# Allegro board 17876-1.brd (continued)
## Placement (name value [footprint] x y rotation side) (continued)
RN5504  SRN100J-3-GP  [SMD-ARES4H18]  57.07 80.09 180 top
RN5701  SRN2K2J-1-GP  [ARES2H16]  14.3 78.64 270 top
RN5702  SRN499F-GP  [ARES8-CN24H20]  14.33 80.67 90 top
RN5703  SRN499F-GP  [ARES8-CN24H20]  14.35 83.26 90 top
RN6301  SRN22J-3-GP-U  [ARES8-CN24-UH20]  83.24 94.18 0 top
RN6302  SRN22J-3-GP-U  [ARES8-CN24-UH20]  78.8 92.06 90 top
RN6502  SRN33J-5-GP-U  [SMD-ARES4H18]  26.16 10.29 90 bottom
RN6503  SRN10KJ-5-GP  [ARES2H18]  24.36 10.42 90 bottom
RN6504  SRN2K2J-1-GP  [ARES2H16]  40.82 14.45 0 top
RN6801  SRN0J-6-GP  [SMD-ARES4H20]  54.71 28.3 0 top
RN6802  SRN10KJ-6-GP  [ARES8-CN24-MUH20]  93.29 16.64 0 top
RN6803  SRN0J-6-GP  [SMD-ARES4H20]  53.16 29.64 0 top
RN6901  SRN2K2J-1-GP  [ARES2H16]  97.89 87.33 180 top
RTC1  ACES-CON2-20-GP-U  [50224-0020N-W02]  156.8 100 270 bottom
SD1  SKT-SDCARD-49-GP-U  [PTFBT4-09GLBS1NN4H2]  2.75 26 90 bottom
SPK1  ACES-CON4-29-GP  [50224-0040N-001]  79.5 98.1 90 bottom
SPR1  SPRING-13-GP-U  [SPR7837H229]  134.5 65 270 bottom
SPR2  SPRING-63-GP  [SPR5630H142]  91 82 90 bottom
SPR3  SPRING-98-GP  [SPR5432H83]  140.94 53.5 0 top
SPR4  SPRING-98-GP  [SPR5432H83]  115.56 39.8 0 top
SPR5  SPRING-98-GP  [SPR5432H83]  111.55 79.45 0 top
SPR6  SPRING-98-GP  [SPR5432H83]  113.27 66.88 270 top
TP501  TPAD14-OP-GP  [TPAD14-OP]  94.49 49.99 270 bottom
TP502  TPAD14-OP-GP  [TPAD14-OP]  94.74 51.22 270 bottom
TP801  TPAD14-OP-GP  [TPAD14-OP]  83.87 42.76 90 top
TP802  TPAD14-OP-GP  [TPAD14-OP]  84.87 41.35 90 top
TP803  TPAD14-OP-GP  [TPAD14-OP]  82.62 42.76 90 top
TP804  TPAD14-OP-GP  [TPAD14-OP]  85.6 47.06 90 top
TP805  TPAD14-OP-GP  [TPAD14-OP]  85.62 45.8 90 top
TP806  TPAD14-OP-GP  [TPAD14-OP]  78.82 39.78 180 top
TP807  TPAD14-OP-GP  [TPAD14-OP]  79.4 42.57 90 top
TP808  TPAD14-OP-GP  [TPAD14-OP]  80.37 41.45 180 top
TP809  TPAD14-OP-GP  [TPAD14-OP]  79.68 38.89 180 top
TP810  TPAD14-OP-GP  [TPAD14-OP]  83.11 35.34 180 bottom
TP811  TPAD14-OP-GP  [TPAD14-OP]  84.38 35.34 180 bottom
TP812  TPAD14-OP-GP  [TPAD14-OP]  72.87 47.03 90 top
TP813  TPAD14-OP-GP  [TPAD14-OP]  71.79 45.97 90 top
TP814  TPAD14-OP-GP  [TPAD14-OP]  85.08 42.56 90 top
TP815  TPAD14-OP-GP  [TPAD14-OP]  82.4 39.7 90 top
TP816  TPAD14-OP-GP  [TPAD14-OP]  86.06 35.79 270 bottom
TP1601  TPAD14-OP-GP  [TPAD14-OP]  78.05 64.97 90 bottom
TP1602  TPAD14-OP-GP  [TPAD14-OP]  76.76 65.25 270 bottom
TP1604  TPAD14-OP-GP  [TPAD14-OP]  82.7 57.86 0 top
TP1605  TPAD14-OP-GP  [TPAD14-OP]  84.35 58.35 90 top
TP1608  TPAD14-OP-GP  [TPAD14-OP]  72.64 56.77 90 top
TP1609  TPAD14-OP-GP  [TPAD14-OP]  76.02 66.24 270 bottom
TP1703  TPAD28-2-GP  [TPAD28]  77.99 59.86 90 top
TP1704  TPAD28-2-GP  [TPAD28]  77.37 60.91 90 top
TP1706  TPAD28-2-GP  [TPAD28]  85.91 59.49 90 top
TP1707  TPAD28-2-GP  [TPAD28]  85.97 57.95 90 top
TP1708  TPAD28-2-GP  [TPAD28]  74.88 64.16 0 top
TP1709  TPAD28-2-GP  [TPAD28]  74.88 62.28 0 top
TP1710  TPAD28-2-GP  [TPAD28]  76.12 63.55 0 top
TP1711  TPAD28-2-GP  [TPAD28]  77.62 62.1 0 top
TP2407  TPAD14-OP-GP  [TPAD14-OP]  60.14 28.84 180 bottom
TP2408  TPAD14-OP-GP  [TPAD14-OP]  50.1 23.12 0 top
TP2409  TPAD14-OP-GP  [TPAD14-OP]  63.61 19.5 180 bottom
TP3301  TPAD14-OP-GP  [TPAD14-OP]  13.63 43.16 180 bottom
TP5201  TPAD14-OP-GP  [TPAD14-OP]  33.17 71.68 0 bottom
TP5301  TPAD28-2-GP  [TPAD28]  133.24 41.23 180 bottom
TP5501  TPAD14-OP-GP  [TPAD14-OP]  62.26 85.16 0 top
TP5701  TPAD14-OP-GP  [TPAD14-OP]  13.07 84.97 0 top
TP6101  TPAD14-OP-GP  [TPAD14-OP]  163.65 80.83 0 top
TP6102  TPAD14-OP-GP  [TPAD14-OP]  163.71 85.08 0 top
TP6301  TPAD14-OP-GP  [TPAD14-OP]  87.12 88.88 180 bottom
TP6302  TPAD14-OP-GP  [TPAD14-OP]  88.61 88.32 180 bottom
TP6303  TPAD14-OP-GP  [TPAD14-OP]  87.38 87.66 180 bottom
TP6304  TPAD14-OP-GP  [TPAD14-OP]  87.33 84.48 180 bottom
TP6305  TPAD14-OP-GP  [TPAD14-OP]  57.89 93.78 180 top
TP6306  TPAD14-OP-GP  [TPAD14-OP]  56.59 93.96 180 top
TP6901  TPAD14-OP-GP  [TPAD14-OP]  100.96 84.25 0 top
TP6902  TPAD14-OP-GP  [TPAD14-OP]  95.46 87.71 0 top
TPAD1  PTWO-CON8-16-GP  [196574-08021-3]  35 9.2 180 bottom
U801  NC7WV07P6X-GP  [SC70-6H44]  87.73 23.32 180 bottom
U2401  NPCE385PB0DX-GP  [LQFP128H63]  50.95 27.15 90 bottom
U2404  G2129TL1U-GP  [SC70-6H44]  61.8 34.04 90 bottom
U2501  MX25U6435FM2I-10G-GP  [SOIC8-1H86]  81.18 19.3 0 bottom
U2502  AP2138N-1D5TRG1-GP  [SOT23-2D8-312H58]  57.99 39.73 90 bottom
U2601  NCT7718W-GP  [MSOP8-1H44]  92.3 22.23 0 bottom
U3301  RTS5170-GR-GP  [QFN24-G2D5H40-U]  11.94 40.13 0 bottom
U3601  G524B2T11U-GP  [SOT-23-5H58]  17.83 63.53 90 bottom
U4001  G2898KD1U-GP  [DFN14J32-G255D95H32]  36.37 26.95 270 bottom
U4002  G2898KD1U-GP  [DFN14J32-G255D95H32]  79.22 80.19 180 bottom
U4003  G2042RD1U-GP  [DFN8F3-G2416-1H32]  58.39 66.4 270 bottom
U5501  G517F1T12U-GP  [SOT-23-5H58]  63.25 79.33 0 bottom
U6001  SN75LVCP601RTJR-GP  [QFN20-G2D25H32]  147.22 54.43 180 bottom
U6301  KLMBG4GEND-B031-GP-U  [BGA153G115130-2H40]  86.2 86.5 0 top
U6304  OZ788WR2IBN-A-0-TR-GP  [CSP97G60-1H41]  53.8 90.07 0 top
U6305  MX25L5121EMC-20G-GP  [SOIC8H69]  32.33 83.52 270 bottom
U6901  LNG2DMTR-GP  [LGA12G2H40]  96.57 84.71 270 top
USB1  SKT-USB13-262-GP  [SKT-USB13-160161]  5.39 54.5 90 bottom
WLAN1  SKT-NGFF75P-47-GP  [NFSA0-S6705-TPH4]  158.65 85.5 90 bottom
X1601  XTAL-48MHZ-62-GP  [OSC-3225-4P-4H36]  61.59 41.73 90 bottom
X1701  XTAL-32D768KHZ-98-GP  [SMD49-12H34]  62.79 64.75 0 bottom
X6301  XTAL-30MHZ-37-GP  [S-OSC3-2016H28]  44.63 93.09 270 top

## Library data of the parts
AFTP2901-AFTP2904 AFTP2906-AFTP2909 AFTP3401-AFTP3404 AFTP4301-AFTP4309 AFTP5402 AFTP6101 AFTP6102 AFTP6104 AFTP6105 AFTP6110 AFTP6111 AFTP6113 AFTP6501-AFTP6518 AFTP6520-AFTP6533 AFTP6601-AFTP6607 = AFTE14P-75: tolerance: ZZ.AFT14.101
BATT1 = 3806K-F10N-03L: tolerance: 020.F0667.0010
C303 = C402H22: tolerance: 78.10421.2FLDL; signal model: wistron_C303
C304 = C402H22: tolerance: 78.10421.2FLDL; signal model: wistron_C304
C801 C802 C804 C1701 = C402H22: tolerance: 78.15124.2FL
C803 C1201 C1220 C1224 C2402 C2403 C2429-C2432 C2436 C2438-C2442 C2444-C2446 C2448 C2501 C2601 C2612 C2704 C2706 C2712 C2714 C2718 C2721 C2724 C2735 C2741 C2743 C3301 C3302 C3306 C3606 C3608 C4012 C5508 C6006 C6018 C6102 C6104 C6301 C6303 C6305 C6306 C6309 C6311 C6312 C6315 C6320 C6327 C6330 C6337 C6341 C6349 C6504 C6505 C6702 C6902 EC6001 PC4513 PC4514 PC4622 = C402H22: tolerance: 78.10421.2FLDL
C1001-C1007 C1010 C1011 C1013 C1015 C1017 C1018 C1022 C1024-C1027 C1035 C1040 C1051 C1067 C1068 C1070 C1071 C1073 PC4710 PC4719 PC5207-PC5212 PC5308-PC5311 PC5407 PC5408 PC6301 PC6304 = C603H40: tolerance: 78.22610.5BLDL
C1008 C1032 C1044 C1077 C1212-C1214 C1219 C1227 C1702 C4011 C4027-C4030 PC5418 = C402H22: tolerance: 78.10523.5FL
C1009 C1021 C1033 C1042 = C402H22: tolerance: 78.18134.1FLDL
C1012 C1014 C1016 C1019 C1020 C1023 C1028-C1030 C1034 C1041 C1043 C1064 C1069 C1072 C1074 = C603H40: tolerance: 78.22610.5BL
C1031 C1045 C1049 C1053 C1056 C1059 C1062 C1065 C1075 C1076 C1215-C1218 C1223 C1226 C2443 C2507 C2508 C3308 C3309 C3609 C4009 C4014 C4018 C5509 PC4404 PC4445 PC4446 PC4610 PC4611 PC4902 PC4903 PC4906 PC5202 PC5302 PC5307 PC5316 PC5419 PC5420 PC6305 = C402H22: tolerance: 78.10523.5FLDL
C1036 C1038 C1079 C1211 EC6602 EC6603 PC5214 PC5321 = C402H22: tolerance: 78.10224.2FL
C1037 C1052 C1055 C1061 C1078 C1221 C1222 C2414 C2416 C2602 C2710 C2711 C2715 C2720 C2722 C2723 C2902 C2907 C2908 C6103 C6307 C6308 C6310 C6313 C6314 C6318 C6335 C6340 C6901 PC4904 PC4905 PC5313 PC5315 PC5318 PC5405 PC5406 PC6302 = C603H36: tolerance: 78.10610.5BLDL
C1039 C1046 C1050 C1054 C1057 C1060 C1063 C1080 C1081 C1202 C4001 C4002 C4005 C4006 C5503 EC2901-EC2904 EC3301 EC4308-EC4313 EC6506 EC6601 PC4407-PC4409 PC4602 PC4609 PC4612-PC4614 = C402H22: tolerance: 78.10224.2FLDL
C1047 C1048 C1058 C1225 C2502 C3305 C4004 C4007 C4010 PC5312 = C603H38: tolerance: 78.10610.5BL
C1066 PC4471 = C402H22: tolerance: 078.22423.05FD
C1203 C1206 C1207 C1210 = C402-TO0D2H28: tolerance: 078.10610.05FD
C1204 C1205 C1208 C1209 = C402-TO0D2H28: tolerance: 78.10610.5FL
C1228 C2417 C2428 C2447 C2606 C6016 PC4501 PC4907 PC5411 = C402H22: tolerance: 78.10421.2FL
C1601 C1602 = C402H22: tolerance: 78.15034.1FLDL
C1603 EC3307 = C402H22: tolerance: 78.6R864.1FL
C1703 C1704 C6343 C6344 FC1001-FC1003 FC1201 FC1202 FC2401 FC6002 FC8901-FC8927 = C402H22: tolerance: 78.18034.1FLDL
C2401 C2725 EC2709-EC2711 EC5505 EC5506 EC6002 PC5401 PC6303 = C402H22: tolerance: 78.22034.1FLDL
C2433 C2708 C2740 C2742 = C603H36: tolerance: 78.22523.5BLDL
C2604 = C402H22: tolerance: 78.47124.2FL
C2605 PC4402 PC4403 = C402H22: tolerance: 78.22224.2FLDL
C2613 C2739 EC2905-EC2908 EC6502 PC4603 PC4615 = C402H22: tolerance: 78.10134.1FLDL
C2701 C2713 C2717 C4003 = C603H36: tolerance: 078.10613.05BD
C2702 C2703 C2707 C6302 C6304 = C402H22: tolerance: 078.47510.05FD
C2705 C2709 = C402H22: tolerance: 78.22510.5FLDL
C3303 = C402H22: tolerance: 78.10321.2FL
C3304 C3307 C5511 C5512 C5514 C5521 C6014 C6015 PC4517 PC4518 = C603H36: tolerance: 78.47520.5BLDL
C3505 = C402H22: tolerance: 78.10421.2FLDL; signal model: wistron_C3505
C3506 = C402H22: tolerance: 78.10421.2FLDL; signal model: wistron_C3506
C3508-C3511 = C402H22: tolerance: 78.1R074.1FL
C3601 C3602 = C805H58: tolerance: 078.22613.051D
C4008 C4013 C4015 C4017 PC4701 PC4709 PC4718 PC4720 PC4901 = C402H22: tolerance: 78.33034.1FL
C4016 = C603H36: tolerance: 78.47520.5BL
C5501 = C402H22: tolerance: 78.10421.2FLDL; signal model: wistron_C5501
C5502 C5519 PC4503 PC4504 PC5201 PC5301 = C805H54: tolerance: 78.47522.51LDL
C5504 EC2701-EC2705 EC4303 EC4304 EC4306 EC4314 EC4315 EC5501-EC5503 EC5701 EC8901-EC8905 PC4302 PC4456 PC4463 PC4464 PC4466 PC4605 PC4623 PC4702 PC4703 PC4711 PC4716 PC5203 PC5206 PC5213 PC5303 PC5306 PC5314 = C402H22: tolerance: 78.10422.5FLDL
C5505 = C402H22: tolerance: 78.10421.2FLDL; signal model: wistron_C5505
C5506 = C402H22: tolerance: 78.10421.2FLDL; signal model: wistron_C5506
C5507 = C402H22: tolerance: 78.10421.2FLDL; signal model: wistron_C5507
C5510 = C402H22: tolerance: 78.10421.2FLDL; signal model: wistron_C5510
C5513 = C402H22: tolerance: 78.10421.2FLDL; signal model: wistron_C5513
C5518 EC1701 EC4307 EC4401 = C402H22: tolerance: 78.10034.1FL
C5520 PC4505 PC4507 PC4508 PC4511 PC4512 = C603H35: tolerance: 78.10424.2BLDL
C5701 = C402H22: tolerance: 78.10421.2FLDL; signal model: wistron_C5701
C5702 = C402H22: tolerance: 78.10421.2FLDL; signal model: wistron_C5702
C5703 = C402H22: tolerance: 78.10421.2FLDL; signal model: wistron_C5703
C5704 = C402H22: tolerance: 78.10421.2FLDL; signal model: wistron_C5704
C5705 = C402H22: tolerance: 78.10421.2FLDL; signal model: wistron_C5705
C5706 = C402H22: tolerance: 78.10421.2FLDL; signal model: wistron_C5706
C5707 = C402H22: tolerance: 78.10421.2FLDL; signal model: wistron_C5707
C5708 = C402H22: tolerance: 78.10421.2FLDL; signal model: wistron_C5708
C6001 = C402H22: tolerance: 78.10324.2FLDL; signal model: wistron_C6001
C6002 = C402H22: tolerance: 78.10324.2FLDL; signal model: wistron_C6002
C6003 = C402H22: tolerance: 78.10324.2FLDL; signal model: wistron_C6003
C6004 = C402H22: tolerance: 78.10324.2FLDL; signal model: wistron_C6004
C6005 = C805H50: tolerance: 78.10623.51LDL
C6007 = C402H22: tolerance: 78.10324.2FLDL; signal model: wistron_C6007
C6008 = C402H22: tolerance: 78.10324.2FLDL; signal model: wistron_C6008
C6009 = C402H22: tolerance: 78.10324.2FLDL; signal model: wistron_C6009
C6010 = C402H22: tolerance: 78.10324.2FLDL; signal model: wistron_C6010
C6011-C6013 = C402H22: tolerance: 78.10520.5FLDL
C6017 = C805H54: tolerance: 78.10623.51L
C6019 = C402H22: tolerance: 78.10324.2FLDL; signal model: wistron_C6019
C6020 = C402H22: tolerance: 78.10324.2FLDL; signal model: wistron_C6020
C6021 = C402H22: tolerance: 78.10324.2FLDL; signal model: wistron_C6021
C6022 = C402H22: tolerance: 78.10324.2FLDL; signal model: wistron_C6022
C6345 = C402H22: tolerance: 78.10324.2FLDL; signal model: wistron_C6345
C6346 = C402H22: tolerance: 78.10324.2FLDL; signal model: wistron_C6346
C6347 = C402H22: tolerance: 78.10324.2FLDL; signal model: wistron_C6347
C6348 = C402H22: tolerance: 78.10324.2FLDL; signal model: wistron_C6348
C6701 = C402H22: tolerance: 78.47321.2FL
C6801 PC4304 PC4419 PC4601 PC4620 = C402H22: tolerance: 78.10324.2FLDL
CPU1 = BGA769M24D5H67: tolerance: 071.00AMD.0D0U
D2402 D2403 D4003 = SOD323AKH38: tolerance: 83.R5003.H8H
D2703 D4001 D4004 D5502 PD4410 Q2501 = SOT-23-9H44: tolerance: 75.00054.A7D
D2901 = SC70-2D2-312H44: tolerance: 075.00054.0G7D
D4002 = SOD323-2513AKH36: tolerance: 83.R2004.J8F
D4301-D4303 PD4303 = SOT23-2D4-312H44: tolerance: 75.00099.O7D
D5501 = SOT23-2D4-312H48: tolerance: 75.00054.E7D
D5701 = SOT23-2D4-312H44: tolerance: 83.00056.Y11
DB1 = PAD-87212-1002N: tolerance: ZZ.00PAD.GV1
DCIN1 = 50224-0060N-W01: tolerance: 20.F1639.006
DIMM1 = 40-42271-26001RHF-WD-U: tolerance: 062.10011.M003
EC1601 = C402H22: tolerance: 78.22034.1FL
EC2401 PC5319 = C402H22: tolerance: 78.10134.1FL
EC2403 = SOD882-10D6-1H20: tolerance: 83.05725.0A0
EC2601 EC2602 EC5510 = C402H22: tolerance: 78.33034.1FLDL
EC4301 EC4302 EC4305 PC4436 = C402H22: tolerance: 78.10034.1FLDL
EC5507 = C402H22: tolerance: 78.6R074.1FLDL
EC6501 EC6503 = C402H22: tolerance: 078.4R7B4.01FD
ED501 = SOD-523-4H28: tolerance: 75.05125.070
ED3301-ED3303 = SOT23-2D4-312H46: tolerance: 75.05125.07D
ED3501-ED3504 = D0201H13: tolerance: 83.00525.0A0
ED3505 ED5501 = SOT-6H58: tolerance: 075.09904.0A7C
ED6001 ED6002 = DFN10G2510H22: tolerance: 075.01043.0073
EL3301 = L125100-4PH24: tolerance: 068.24900.2001; signal model: Graser_EL3301
EL3503 = L125100-4PH24: tolerance: 068.24900.2001; signal model: Graser_EL3503
EL4301-EL4304 PR4406 PR4415 PR4432 PR4442 PR4447 PR4457 PR4467 PR4470 PR4471 PR4474-PR4476 PR4502 PR4514 PR4617 PR4621 PR5204 PR5209 PR5307 PR5409 PR5411-PR5413 R501 R704 R816 R818 R821 R823 R1201 R1202 R1208 R1210 R1625 R1632-R1634 R1730 R1731 R1734 R1737 R2413-R2415 R2425 R2435 R2440 R2476 R2477 R2486 R2488 R2494 R2601 R2603 R2609 R2613 R2708 R2709 R2712 R2718 R2720 R2734 R2741 R2752 R3302 R3309 R3311 R3503-R3506 R4001 R4005 R4007 R4008 R4012 R4016 R4301 R5501-R5503 R5702 R5712 R6001 R6502 R6514 R6515 = 0R0402-PAD: tolerance: ZZ.R0402.ZZZ
EL5501 = L125100-4PH24: tolerance: 068.24900.2001; signal model: wistron_EL5501
EL5502 = L125100-4PH24: tolerance: 068.24900.2001; signal model: wistron_EL5502
EL6101 = L125100-4PH24: tolerance: 068.24900.2001; signal model: wistron_EL6101
EL6602 = L125100-4PH24: tolerance: 068.24900.2001; signal model: wistron_EL6602
EL6603 = L125100-4PH24: tolerance: 068.24900.2001; signal model: wistron_EL6603
EL6604 = L125100-4PH24: tolerance: 068.24900.2001; signal model: wistron_EL6604
ER5714-ER5717 R802 = R402H16: tolerance: 64.15005.6DL
F5501 = POLYSW-4633-UH43: tolerance: 69.50007.A31
F5502 F5503 F5701 = POLYSW-2114H30: tolerance: 69.48001.081
FC1601 = C402H22: tolerance: 78.8R064.1FLDL
G1701 G1702 = CON2O-U: tolerance: ZZ.CON2O.XXX
H1 = HOLE354R237: tolerance: ZZ.PAD01.041
H4 H9 = HOLE335R197: tolerance: ZZ.00PAD.7L1
H10-H13 = HOLE276R178: tolerance: ZZ.00PAD.N11
H14 = HOLE335R142: tolerance: ZZ.00PAD.XXX
HDA27 = QFN40J5-G3D75H36: tolerance: 071.03204.0003
HDD1 = 15-02330-3A03-A: tolerance: 022.10019.00F1
HDMI1 = SKT-HDMI23-188125-5: tolerance: 022.10025.00F1
HDT1 = DM-ASP-137098-05-01: tolerance: ZZ.F1722.02001
IOBD1 = 132F44-000000-A2-R: tolerance: 020.K0228.0044
KB1 = 50699-03001-W01: tolerance: 020.K0254.0030
LCD1 = 51540-04001-W01: tolerance: 20.K0678.040
LIDSW1 = SOT23-2D8-123H52: tolerance: 74.05712.0BB
PC4301 PC4435 = C603H36: tolerance: 078.10524.05BD
PC4303 PC4305 = C402H22: tolerance: 78.10324.2FL
PC4306 PC4401 PC4410 PC4411 PC4418 PC4427 PC4438 PC4452 PC4453 PC4459 PC4509 PC4510 PC4704-PC4707 PC4712-PC4715 PC5204 PC5205 PC5304 PC5305 = C805H58: tolerance: 78.10622.51LDL
PC4405 = C402H22: tolerance: 78.22321.2FL
PC4406 = C402H22: tolerance: 78.56124.2FLDL
PC4431 = C603H36: tolerance: 78.22422.2BLDL
PC4433 = C603H36: tolerance: 78.47422.5BLDL
PC4461 PC4462 PC4467 PC4468 = C402H22: tolerance: 78.22224.L0L
PC4502 = C402H22: tolerance: 78.68034.1FL
PC4506 = C805H56: tolerance: 78.10622.51L
PC4515 PC4516 = C402H22: tolerance: 78.18034.1FL
PC4604 PC4616 = C402H22: tolerance: 078.39124.02FD
PC4606 PC4618 = C402H22: tolerance: 078.33322.02FD
PC4607 PC4619 = C402H22: tolerance: 078.47322.02FD
PC4608 PC4617 = C402H22: tolerance: 78.33124.2FLDL
PC4621 = C402H22: tolerance: 78.33124.2FL
PC4708 PC4717 = C402H22: tolerance: 078.22422.05FD
PC5317 PC5320 PC5410 = C402H22: tolerance: 78.10422.5FL
PC5412 = C402H22: tolerance: 78.68124.2FL
PD4301 = DO214AAAKH97: tolerance: 83.P6SMB.JAG
PD4302 = SOD123AK-2H43: tolerance: 83.SMF18.AAH
PD4304 = SOT23-2D4-312H46: tolerance: 75.04024.07D
PD4404 = SOD323AKH44: tolerance: 83.00355.G1F
PD5201 PD5301 = SOD323AKH40: tolerance: 083.04024.0AA1
PG4407 PG4426 PG4428 PG4429 PG4524 PG4525 PG4602-PG4608 PG4903 PG5201-PG5211 PG5301-PG5312 PG5314 PG5315 PG5401-PG5406 PG5411 = GAP-CLOSE-PWR-3: tolerance: ZZ.CLOSE.001
PG4501-PG4523 PG4601 PG4609-PG4611 PG4701-PG4713 PG4901 PG4902 PG5212 PG5313 = GAP-CLOSE-PWR: tolerance: ZZ.CLOSE.011
PL4401 = L7066-1830-UH119: tolerance: 68.4R71A.20H
PL4501 PL4502 = L7066-1830-UH119: tolerance: 68.2R210.20B
PL4701 PL4702 = L7366-1930H119: tolerance: 068.R1510.2041
PL5201 PL5301 = L7066-1830-UH119: tolerance: 68.1R01A.20B
PL5401 = L2520-D620H48: tolerance: 068.1R010.1281
PL6301 = L2520-D620H48: tolerance: 068.2R210.1231
PQ4301 = SOT23DGS2D4H48: tolerance: 084.00301.0031
PQ4302 Q2601 Q5501 Q5503 Q5708 = SOT23CBE2D4H44: tolerance: 84.T3904.H11
PQ4304 PQ4415 = SC70-2D2-312H44: tolerance: 84.00024.A1K
PQ4305 PQ4416 = SC70-2D2-312H44: tolerance: 84.00024.01K
PQ4309 PQ4402 PQ4412 Q2402 Q2403 Q2405 Q2502 Q2505 Q2507 Q2603 Q2901 Q4001 Q5401 Q5701 Q5707 Q6502 = SOT23DGS2D4H44: tolerance: 84.2N702.J31
PQ4401 PQ4408 PU4301 = PPAK-8P-3232H36: tolerance: 84.07403.037
PQ4405 PQ4414 Q1701 Q1702 Q2604 Q7001 = SOT-363H44: tolerance: 75.27002.F7C
PQ4413 Q2401 = SOT23CBE2D4H44: tolerance: 84.T3906.E11
PQ4901 Q6507 = SOT-363H44: tolerance: 84.2N702.A3F
PR4302 = R402H16: tolerance: 64.15025.6DL
PR4303 PR5312 PR5314 PR5414 R1613-R1616 R1620 R1621 R1636 R1702 R1703 R1707-R1710 R1713 R1715 R1717 R1718 R1723 R1724 R1733 R1735 R1738 R1757 R1759-R1761 R2001-R2006 R2400 R2407 R2420-R2423 R2427 R2428 R2436 R2444 R2463 R2471 R2472 R2474 R2478 R2490 R2497 R2499 R2507 R3307 R4006 R4010 R4011 R4013 R5527 R5701 R6002-R6009 R6111 R6112 R6309 R6347 R6348 R6354-R6357 R6359 R6364 R6902 R6905 R7005 = R402H16: tolerance: 63.10334.1DL
PR4306 R5516 R5521 R5526 R6512 = R402H16: tolerance: 63.22234.1DL
PR4307 R1729 R5504 R6804 = R402H16: tolerance: 63.33034.1DL
PR4309 = R603H22: tolerance: 63.24434.15L
PR4310 = R603H22: tolerance: 63.47333.15L
PR4311 PR4409 PR4417 PR4431 PR4441 PR4472 PR4478 PR4513 PR5203 PR5303 PR5407 R1719 R1747 R1758 R2410 R2434 R2442 R2473 R2516 R2518 R2702 R2710 R2716 R2717 R2905 R3605 R5505-R5508 R5522 R5709 R5719 R6345 R6520 R6701 R7002 = R402H16: tolerance: 63.10434.1DL
PR4312 PR4444 R504 R801 R809 R811 R812 R822 R1206 R1711 R1748 R2419 R2443 R2468 R2493 R2501 R2506 R2735 R2921 R2922 R4003 R6503 R6516 = R402H16: tolerance: 63.10234.1DL
PR4316 = R1206H28: tolerance: 63.33232.11L
PR4401 PR4402 R2711 R5711 = R402H16: tolerance: 64.20035.6DL
PR4403 PR4507 = R402H16: tolerance: 64.95325.6DL
PR4404 = R402H16: tolerance: 64.82525.6DL
PR4405 = R402H16: tolerance: 64.16535.6DL
PR4407 = R402H14: tolerance: 64.10005.6DL
PR4410 = R402H16: tolerance: 64.71515.6DL
PR4412 = NTC-402H24-U: tolerance: 69.60028.001
PR4413 PR4436 PR4439 PR4450 PR4451 R2438 = R402H16: tolerance: 64.10035.6DL
PR4416 = R402H16: tolerance: 64.23725.6DL
PR4418 = R402H16: tolerance: 64.19135.6DL
PR4420 PR4422 PR4435 PR4448 PR4449 PR4508 PR4512 PR4611 PR4620 PR4630 PR4901 PR5208 PR5309 PR5316 = R402H16: tolerance: 64.10025.6DL
PR4426 PR4443 = R3720H40: tolerance: 64.R0105.7FL
PR4428 R2409 R2703-R2706 R2715 R2742 R2743 R2745 R2747 R2749 R2906 R2907 R2909 R2911 R6105 R6324 R6325 = 0R0603-PAD: tolerance: ZZ.R0603.ZZZ
PR4433 = R402H16: tolerance: 64.68035.6DL
PR4434 = R402H16: tolerance: 64.30035.L0L
PR4437 PR4456 PR4468 = R402H16: tolerance: 64.2R005.6DL
PR4438 = R603H22: tolerance: 64.4R705.55L
PR4440 = R603H22: tolerance: 63.20333.15L
PR4445 R6360 R6361 = R402H16: tolerance: 63.47434.1DL
PR4446 PR4481 PR4509 PR4510 PR5206 PR5306 PR5319 PR5410 R1205 R1207 R1209 R1211 R1635 R1756 R2498 R2513-R2515 R2517 R2602 R2607 R4004 R4009 R4015 R5524 R6106-R6110 R6113 R6327 R6328 R6501 R6510 R6513 R6518 R6803 R6901 R6903 R6933-R6937 R7001 = R402H16: tolerance: 63.R0034.1DL
PR4452 R5710 = R402H16: tolerance: 64.15035.6DL
PR4454 = R805H24: tolerance: 64.10005.16L
PR4477 R1203 R1204 R1601 R1602 R1609 R1610 = R402H16: tolerance: 64.10015.6DL
PR4503 PR4504 = R603H22: tolerance: 64.1R505.55L
PR4505 = R402H16: tolerance: 64.69815.6DL
PR4506 = R402H16: tolerance: 64.13735.6DL
PR4511 = R402H16: tolerance: 64.15425.6DL
PR4601 PR5201 PR5301 R2908 R2910 = R402H14: tolerance: 64.10R05.6DL
PR4602 PR4624 = R402H16: tolerance: 64.30105.6DL
PR4603 = R402H16: tolerance: 64.39005.6DL
PR4604 PR4627 = R402H16: tolerance: 64.68025.6DL
PR4605 = R402H16: tolerance: 64.21515.6DL
PR4606 PR4625 PR4632 = R402H16: tolerance: 64.26115.6DL
PR4607 PR4628 R803 R2606 = R402H16: tolerance: 64.20015.6DL
PR4608 = R402H16: tolerance: 64.34025.6DL
PR4609 PR4633 = R402H16: tolerance: 64.11025.6DL
PR4610 PR4635 = NTC-402H22-U: tolerance: 69.60011.201
PR4612 PR4622 R1603 = R402H16: tolerance: 64.11825.6DL
PR4613 PR4623 = NTC-402H22-U: tolerance: 69.60011.101
PR4614 PR4626 = R402H16: tolerance: 64.27425.6DL
PR4615 PR4618 = R402H16: tolerance: 64.13335.6DL
PR4616 = R603H22: tolerance: 63.1R033.15L
PR4619 R808 = R402H16: tolerance: 63.30134.1DL
PR4629 = R402H16: tolerance: 64.21035.6DL
PR4631 PR4634 = R402H14: tolerance: 63.10034.1DL
PR4636 = R402H16: tolerance: 64.48705.6DL
PR4701 PR4704 R2408 = R603H22: tolerance: 64.2R205.55L
PR4702 PR4705 = R402H16: tolerance: 64.36515.6DL
PR4703 PR4706 = R402H16: tolerance: 64.1R005.6DL
PR4902 = R402H16: tolerance: 64.39015.6DL
PR4903 = R402H16: tolerance: 64.30015.6DL
PR5202 = R402H16: tolerance: 64.82015.6DL
PR5205 PR5304 = R402H16: tolerance: 64.51035.6DL
PR5207 = R402H16: tolerance: 64.26715.6DL
PR5210 PR5317 = R603H22: tolerance: 64.2R005.55L
PR5211 PR5318 = R805H24: tolerance: 64.2R205.16L
PR5302 = R402H16: tolerance: 64.64915.6DL
PR5308 = R402H16: tolerance: 64.60415.6DL
PR5310 = R603H22: tolerance: 63.5R133.15L
PR5311 PR5313 R2701 R2707 R2751 = 0R0805-PAD: tolerance: ZZ.R0805.ZZZ
PR5315 = R402H16: tolerance: 64.21525.6DL
PR5403 = R402H16: tolerance: 64.10235.6DL
PR5405 = R402H16: tolerance: 64.51025.6DL
PR5406 = R402H16: tolerance: 64.18025.6DL
PR6301 = R402H16: tolerance: 64.21025.6DL
PR6302 = R402H16: tolerance: 64.14325.6DL
PR6303 R2914 = R603H22: tolerance: 63.R0033.L0L
PT4501 PT4502 = CT7343H83: tolerance: 077.51571.0001
PT4701 PT4702 PT4705 PT4706 = CT7343H83: tolerance: 79.33719.20C
PT4707 PT4708 = CT7343H83: tolerance: 79.33612.20L
PU4401 = QFN32J4-G2D7H42: tolerance: 074.88739.0073
PU4411 PU4412 PU4502-PU4504 = PPAK-8P-3232H36: tolerance: 084.07408.0037
PU4501 = QFN20-G1D75H32: tolerance: 074.06575.0A43
PU4505 = PPAK-8P-3232H36: tolerance: 84.07506.037
PU4601 = QFN40-G3D5H32: tolerance: 74.62771.033
PU4701 PU4702 PU4705 PU4706 = PPAK-8P-G5324H44-COLAY: tolerance: ZZ.00215.037
PU4901 = SOIC8-G3530H63: tolerance: 074.05337.0031
PU5201 PU5301 = QFN32J4-G3PH32: tolerance: 074.05388.0043
PU5302 = SOIC8-G3530H63: tolerance: 074.05934.003D
PU5401 = DFN8-G125065H32: tolerance: 074.05797.0073
PU5402 = SOT-23-5H40: tolerance: 074.09078.003F
PU6301 = DFN8G2-G1711H26: tolerance: 74.00232.033
Q801 Q6508 = SOT-363H44: tolerance: 075.00138.0A7C
Q2404 Q2506 Q6503 Q6504 = SOT23DGS2D4H48: tolerance: 084.02421.0031
Q5703 = SOT23DGS2D4H48: tolerance: 084.00301.0031; signal model: wistron_Q5703
Q5705 = SOT23DGS2D4H48: tolerance: 084.00301.0031; signal model: wistron_Q5705
Q6301 = SOT23DGS2D4H48: tolerance: 84.05067.031
Q6501 = SOT23CBE2D4H44: tolerance: 084.00144.0B11
R301 R302 = R402H16: tolerance: 64.19605.6DL
R503 = R402H16: tolerance: 64.39R25.6DL
R810 = 0R0402-PAD: tolerance: ZZ.R0402.ZZZ; signal model: Graser_R810
R813 = 0R0402-PAD: tolerance: ZZ.R0402.ZZZ; signal model: Graser_R813
R820 = 0R0402-PAD: tolerance: ZZ.R0402.ZZZ; signal model: Graser_R820
R1607 = 0R0402-PAD: tolerance: ZZ.R0402.ZZZ; signal model: wistron_R1607
R1608 = 0R0402-PAD: tolerance: ZZ.R0402.ZZZ; signal model: wistron_R1608
R1611 = 0R0402-PAD: tolerance: ZZ.R0402.ZZZ; signal model: wistron_R1611
R1612 = R402H16: tolerance: 63.R0034.1DL; signal model: wistron_R1612
R1617 = 0R0402-PAD: tolerance: ZZ.R0402.ZZZ; signal model: wistron_R1617
R1618 = 0R0402-PAD: tolerance: ZZ.R0402.ZZZ; signal model: wistron_R1618
R1619 = 0R0402-PAD: tolerance: ZZ.R0402.ZZZ; signal model: wistron_R1619
R1624 R4014 R6353 = R402H16: tolerance: 63.10534.1DL
R1629 = R402H16: tolerance: 63.33034.1DL; signal model: wistron_R1629
R1630 = 0R0402-PAD: tolerance: ZZ.R0402.ZZZ; signal model: wistron_R1630
R1631 = 0R0402-PAD: tolerance: ZZ.R0402.ZZZ; signal model: wistron_R1631
R1721 = R402H16: tolerance: 63.15334.1DL
R1745 = R603H22: tolerance: 63.20634.15L
R1746 = R402H16: tolerance: 63.20334.1DL
R2007-R2012 R2615 = R402H16: tolerance: 63.20234.1DL
R2437 R2492 = R402H16: tolerance: 63.47334.1DL
R2465 = R402H16: tolerance: 64.22125.6DL
R2475 = R402H16: tolerance: 63.82234.1DL
R2489 R2491 = R402H16: tolerance: 63.33434.1DL
R2505 = R402H16: tolerance: 63.10634.1DL
R2540 R2912 R2928 R6010-R6013 R6313 R6346 R6504 = R402H16: tolerance: 63.47234.1DL
R2604 R2612 = NTC-603H38: tolerance: 69.60035.041
R2605 = R402H16: tolerance: 64.18725.6DL
R2608 R2614 = R402H16: tolerance: 64.24925.6DL
R2753 = 0R0402-PAD: tolerance: ZZ.R0402.ZZZ; signal model: wistron_R2753
R2901-R2904 = L1608-UH38: tolerance: 68.00230.041
R3303 = 0R0402-PAD: tolerance: ZZ.R0402.ZZZ; signal model: wistron_R3303
R3304 = R402H16: tolerance: 64.62015.6DL
R4002 = R402H16: tolerance: 63.20434.1DL
R5533 R5534 R6014 R6015 = R805H24: tolerance: 63.R0031.16L
R6016 = R402H16: tolerance: 63.R0034.1DL; signal model: wistron_R6016
R6017 = R402H16: tolerance: 63.R0034.1DL; signal model: wistron_R6017
R6018 = R402H16: tolerance: 63.R0034.1DL; signal model: wistron_R6018
R6019 = R402H16: tolerance: 63.R0034.1DL; signal model: wistron_R6019
R6101 = 0R0402-PAD: tolerance: ZZ.R0402.ZZZ; signal model: wistron_R6101
R6104 = 0R0402-PAD: tolerance: ZZ.R0402.ZZZ; signal model: wistron_R6104
R6312 = R402H16: tolerance: 63.22034.1DL; signal model: wistron_R6312
R6343 = R402H16: tolerance: 63.R0034.1DL; signal model: wistron_R6343
R6344 = R402H16: tolerance: 63.22034.1DL; signal model: wistron_R6344
R6365 = R402H16: tolerance: 63.68134.1DL
R6505 R6506 = R402H16: tolerance: 63.22134.1DL
R6801 = R402H16: tolerance: 63.R0034.1DL; signal model: wistron_R6801
R6802 = R402H16: tolerance: 63.R0034.1DL; signal model: wistron_R6802
RN803 RN804 = ARES8-CN24H20: tolerance: 66.10236.08L
RN806-RN809 RN1709 = SMD-ARES4H18: tolerance: 66.10236.04L
RN810 = SMD-ARES4H20: tolerance: 66.R0036.04L
RN811 = SMD-ARES4H18: tolerance: 66.47236.04L
RN1601 RN1705 RN1710 RN2407 RN6503 = ARES2H18: tolerance: 66.10336.04L
RN1603 = SMD-ARES4H20: tolerance: 66.R0036.04L; signal model: Graser_RN1603
RN1604 = SMD-ARES4H20: tolerance: 66.R0036.04L; signal model: wistron_RN1604
RN1605 = SMD-ARES4H20: tolerance: 66.R0036.04L; signal model: wistron_RN1605
RN1606 = SMD-ARES4H20: tolerance: 66.R0036.04L; signal model: wistron_RN1606
RN1701 RN1703 RN1704 RN2401 RN2404 RN2601 RN2901 RN5701 RN6504 RN6901 = ARES2H16: tolerance: 66.22236.04L
RN1706 RN2403 = SMD-ARES4: tolerance: 66.10436.04L
RN1707 = ARES8-CN24-UH20: tolerance: 66.33036.A8L; signal model: wistron_RN1707
RN1708 = SMD-ARES4H18: tolerance: 66.15336.04L
RN2405 = SMD-ARES4H20: tolerance: 66.R0036.04L; signal model: wistron_RN2405
RN2406 = SMD-ARES4H20: tolerance: 66.R0036.04L; signal model: wistron_RN2406
RN4301 RN4302 RN5503 RN5504 = SMD-ARES4H18: tolerance: 66.10136.04L
RN5502 RN6502 = SMD-ARES4H18: tolerance: 66.33036.04L
RN5702 RN5703 = ARES8-CN24H20: tolerance: 66.49156.08L
RN6301 = ARES8-CN24-UH20: tolerance: 66.22036.08L; signal model: wistron_RN6301
RN6302 = ARES8-CN24-UH20: tolerance: 66.22036.08L; signal model: wistron_RN6302
RN6801 = SMD-ARES4H20: tolerance: 66.R0036.04L; signal model: wistron_RN6801
RN6802 = ARES8-CN24-MUH20: tolerance: 66.10336.08L
RN6803 = SMD-ARES4H20: tolerance: 66.R0036.04L; signal model: wistron_RN6803
RTC1 = 50224-0020N-W02: tolerance: 20.F1639.002
SD1 = PTFBT4-09GLBS1NN4H2: tolerance: 062.10002.0081
SPK1 = 50224-0040N-001: tolerance: 20.F1639.004
SPR1 = SPR7837H229: tolerance: 34.43E24.001
SPR2 = SPR5630H142: tolerance: 34.4Y806.001
SPR3-SPR6 = SPR5432H83: tolerance: 34.34S02.002
TP501 TP502 TP801-TP816 TP1601 TP1602 TP1604 TP1605 TP1608 TP1609 TP2407-TP2409 TP3301 TP5201 TP5501 TP5701 TP6101 TP6102 TP6301-TP6306 TP6901 TP6902 = TPAD14-OP: tolerance: ZZ.PAD14.001
TP1703 TP1704 TP1706-TP1711 TP5301 = TPAD28: tolerance: ZZ.PAD28.XXX
TPAD1 = 196574-08021-3: tolerance: 020.K0255.0008
U801 = SC70-6H44: tolerance: 73.7WV07.00J
U2401 = LQFP128H63: tolerance: 071.00385.0A0G
U2404 = SC70-6H44: tolerance: 73.02129.02J
U2501 = SOIC8-1H86: tolerance: 72.25643.B01
U2502 = SOT23-2D8-312H58: tolerance: 74.02138.03B
U2601 = MSOP8-1H44: tolerance: 74.07718.0B9
U3301 = QFN24-G2D5H40-U: tolerance: 71.05170.003
U3601 = SOT-23-5H58: tolerance: 074.00524.0C9F
U4001 U4002 = DFN14J32-G255D95H32: tolerance: 074.02898.0093
U4003 = DFN8F3-G2416-1H32: tolerance: 074.02042.0093
U5501 = SOT-23-5H58: tolerance: 074.51712.009F
U6001 = QFN20-G2D25H32: tolerance: 71.75601.003
U6301 = BGA153G115130-2H40: tolerance: 072.KMBG4.0C0U
U6304 = CSP97G60-1H41: tolerance: 071.07882.000U
U6305 = SOIC8H69: tolerance: 72.25512.J01
U6901 = LGA12G2H40: tolerance: 074.LNG2D.00BZ
USB1 = SKT-USB13-160161: tolerance: 022.10005.02V1
WLAN1 = NFSA0-S6705-TPH4: tolerance: 062.10003.0141
X1601 = OSC-3225-4P-4H36: tolerance: 082.30028.0101
X1701 = SMD49-12H34: tolerance: 082.30003.0301
X6301 = S-OSC3-2016H28: tolerance: 082.30002.0111

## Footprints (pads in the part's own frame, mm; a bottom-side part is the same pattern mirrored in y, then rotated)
0R0402-PAD
  custom 0.127x0.127 smd: 1(0,0.432) 2(0,-0.432)
0R0603-PAD
  custom 0.254x0.254 smd: 1(0,0.66) 2(0,-0.66)
0R0805-PAD
  rect 1.549x1.346 smd: 1(0,0.838) 2(0,-0.838)
15-02330-3A03-A
  oval 1.727x2.794 hole 1.016x2.083: 23(-18.6,0) 24(18.6,0)
  oval 1.041x1.168 hole 0.762: P1(-1.905,0.4) P2(-0.635,0.4) P3(0.635,0.4) P4(1.905,0.4) P5(3.175,0.4) P6(4.445,0.4) P7(5.715,0.4) P8(6.985,0.4) P9(8.255,0.4) P10(9.525,0.4) P11(10.795,0.4) P12(12.065,0.4) P13(13.335,0.4) P14(14.605,0.4) P15(15.875,0.4) S1(-15.875,0.4) S2(-14.605,0.4) S3(-13.335,0.4) S4(-12.065,0.4) S5(-10.795,0.4) S6(-9.525,0.4) S7(-8.255,0.4)
40-42271-26001RHF-WD-U
  round 0.254 hole 1.6 unplated: (-34.4,0)
  round 0.254 hole 1.118 unplated: (34.4,0)
  custom 0.089x0.089 smd: 1(-33.375,-4.1) 2(-33.125,4.1) 3(-32.875,-4.1) 4(-32.625,4.1) 5(-32.375,-4.1) 6(-32.125,4.1) 7(-31.875,-4.1) 8(-31.625,4.1) 9(-31.375,-4.1) 10(-31.125,4.1) 11(-30.875,-4.1) 12(-30.625,4.1) 13(-30.375,-4.1) 14(-30.125,4.1) 15(-29.875,-4.1) 16(-29.625,4.1) 17(-29.375,-4.1) 18(-29.125,4.1) 19(-28.875,-4.1) 20(-28.625,4.1) 21(-28.375,-4.1) 22(-28.125,4.1) 23(-27.875,-4.1) 24(-27.625,4.1) 25(-27.375,-4.1) 26(-27.125,4.1) 27(-26.875,-4.1) 28(-26.625,4.1) 29(-26.375,-4.1) 30(-26.125,4.1) 31(-25.875,-4.1) 32(-25.625,4.1) 33(-25.375,-4.1) 34(-25.125,4.1) 35(-24.875,-4.1) 36(-24.625,4.1) 37(-24.375,-4.1) 38(-24.125,4.1) 39(-23.875,-4.1) 40(-23.625,4.1) 41(-23.375,-4.1) 42(-23.125,4.1) 43(-22.875,-4.1) 44(-22.625,4.1) 45(-22.375,-4.1) 46(-22.125,4.1) 47(-21.875,-4.1) 48(-21.625,4.1) 49(-21.375,-4.1) 50(-21.125,4.1) 51(-20.875,-4.1) 52(-20.625,4.1) 53(-20.375,-4.1) 54(-20.125,4.1) 55(-19.875,-4.1) 56(-19.625,4.1) 57(-19.375,-4.1) 58(-19.125,4.1) 59(-18.875,-4.1) 60(-18.625,4.1) 61(-18.375,-4.1) 62(-18.125,4.1) 63(-17.875,-4.1) 64(-17.625,4.1) 65(-17.375,-4.1) 66(-17.125,4.1) 67(-16.875,-4.1) 68(-16.625,4.1) 69(-16.375,-4.1) 70(-16.125,4.1) 71(-15.875,-4.1) 72(-15.625,4.1) 73(-15.375,-4.1) 74(-15.125,4.1) 75(-14.875,-4.1) 76(-14.625,4.1) 77(-14.375,-4.1) 78(-14.125,4.1) 79(-13.875,-4.1) 80(-13.625,4.1) 81(-13.375,-4.1) 82(-13.125,4.1) 83(-12.875,-4.1) 84(-12.625,4.1) 85(-12.375,-4.1) 86(-12.125,4.1) 87(-11.875,-4.1) 88(-11.625,4.1) 89(-11.375,-4.1) 90(-11.125,4.1) 91(-10.875,-4.1) 92(-10.625,4.1) 93(-10.375,-4.1) 94(-10.125,4.1) 95(-9.875,-4.1) 96(-9.625,4.1) 97(-9.375,-4.1) 98(-9.125,4.1) 99(-8.875,-4.1) 100(-8.625,4.1) 101(-8.375,-4.1) 102(-8.125,4.1) 103(-7.875,-4.1) 104(-7.625,4.1) 105(-7.375,-4.1) 106(-7.125,4.1) 107(-6.875,-4.1) 108(-6.625,4.1) 109(-6.375,-4.1) 110(-6.125,4.1) 111(-5.875,-4.1) 112(-5.625,4.1) 113(-5.375,-4.1) 114(-5.125,4.1) 115(-4.875,-4.1) 116(-4.625,4.1) 117(-4.375,-4.1) 118(-4.125,4.1) 119(-3.875,-4.1) 120(-3.625,4.1) 121(-3.375,-4.1) 122(-3.125,4.1) 123(-2.875,-4.1) 124(-2.625,4.1) 125(-2.375,-4.1) 126(-2.125,4.1) 127(-1.875,-4.1) 128(-1.625,4.1) 129(-1.375,-4.1) 130(-1.125,4.1) 131(-0.875,-4.1) 132(-0.625,4.1) 133(-0.375,-4.1) 134(-0.125,4.1) 135(0.125,-4.1) 136(0.375,4.1) 137(0.625,-4.1) 138(0.875,4.1) 139(1.125,-4.1) 140(1.375,4.1) 141(1.625,-4.1) 142(1.875,4.1) 143(2.125,-4.1) 144(2.375,4.1) 145(4.625,-4.1) 146(4.875,4.1) 147(5.125,-4.1) 148(5.375,4.1) 149(5.625,-4.1) 150(5.875,4.1) 151(6.125,-4.1) 152(6.375,4.1) 153(6.625,-4.1) 154(6.875,4.1) 155(7.125,-4.1) 156(7.375,4.1) 157(7.625,-4.1) 158(7.875,4.1) 159(8.125,-4.1) 160(8.375,4.1) 161(8.625,-4.1) 162(8.875,4.1) 163(9.125,-4.1) 164(9.375,4.1) 165(9.625,-4.1) 166(9.875,4.1) 167(10.125,-4.1) 168(10.375,4.1) 169(10.625,-4.1) 170(10.875,4.1) 171(11.125,-4.1) 172(11.375,4.1) 173(11.625,-4.1) 174(11.875,4.1) 175(12.125,-4.1) 176(12.375,4.1) 177(12.625,-4.1) 178(12.875,4.1) 179(13.125,-4.1) 180(13.375,4.1) 181(13.625,-4.1) 182(13.875,4.1) 183(14.125,-4.1) 184(14.375,4.1) 185(14.625,-4.1) 186(14.875,4.1) 187(15.125,-4.1) 188(15.375,4.1) 189(15.625,-4.1) 190(15.875,4.1) 191(16.125,-4.1) 192(16.375,4.1) 193(16.625,-4.1) 194(16.875,4.1) 195(17.125,-4.1) 196(17.375,4.1) 197(17.625,-4.1) 198(17.875,4.1) 199(18.125,-4.1) 200(18.375,4.1) 201(18.625,-4.1) 202(18.875,4.1) 203(19.125,-4.1) 204(19.375,4.1) 205(19.625,-4.1) 206(19.875,4.1) 207(20.125,-4.1) 208(20.375,4.1) 209(20.625,-4.1) 210(20.875,4.1) 211(21.125,-4.1) 212(21.375,4.1) 213(21.625,-4.1) 214(21.875,4.1) 215(22.125,-4.1) 216(22.375,4.1) 217(22.625,-4.1) 218(22.875,4.1) 219(23.125,-4.1) 220(23.375,4.1) 221(23.625,-4.1) 222(23.875,4.1) 223(24.125,-4.1) 224(24.375,4.1) 225(24.625,-4.1) 226(24.875,4.1) 227(25.125,-4.1) 228(25.375,4.1) 229(25.625,-4.1) 230(25.875,4.1) 231(26.125,-4.1) 232(26.375,4.1) 233(26.625,-4.1) 234(26.875,4.1) 235(27.125,-4.1) 236(27.375,4.1) 237(27.625,-4.1) 238(27.875,4.1) 239(28.125,-4.1) 240(28.375,4.1) 241(28.625,-4.1) 242(28.875,4.1) 243(29.125,-4.1) 244(29.375,4.1) 245(29.625,-4.1) 246(29.875,4.1) 247(30.125,-4.1) 248(30.375,4.1) 249(30.625,-4.1) 250(30.875,4.1) 251(31.125,-4.1) 252(31.375,4.1) 253(31.625,-4.1) 254(31.875,4.1) 255(32.125,-4.1) 256(32.375,4.1) 257(32.625,-4.1) 258(32.875,4.1) 259(33.125,-4.1) 260(33.375,4.1)
  rect 3.505x4.597 smd: 261(33.8,-12) 262(-33.8,-12)
132F44-000000-A2-R
  rect 0.305x1.092 smd: 1(-10.75,3.3) 2(-10.25,3.3) 3(-9.75,3.3) 4(-9.25,3.3) 5(-8.75,3.3) 6(-8.25,3.3) 7(-7.75,3.3) 8(-7.25,3.3) 9(-6.75,3.3) 10(-6.25,3.3) 11(-5.75,3.3) 12(-5.25,3.3) 13(-4.75,3.3) 14(-4.25,3.3) 15(-3.75,3.3) 16(-3.25,3.3) 17(-2.75,3.3) 18(-2.25,3.3) 19(-1.75,3.3) 20(-1.25,3.3) 21(-0.75,3.3) 22(-0.25,3.3) 23(0.25,3.3) 24(0.75,3.3) 25(1.25,3.3) 26(1.75,3.3) 27(2.25,3.3) 28(2.75,3.3) 29(3.25,3.3) 30(3.75,3.3) 31(4.25,3.3) 32(4.75,3.3) 33(5.25,3.3) 34(5.75,3.3) 35(6.25,3.3) 36(6.75,3.3) 37(7.25,3.3) 38(7.75,3.3) 39(8.25,3.3) 40(8.75,3.3) 41(9.25,3.3) 42(9.75,3.3) 43(10.25,3.3) 44(10.75,3.3)
  rect 0.813x2.007 smd: 45(-12.45,0) 46(12.45,0)
3806K-F10N-03L
  rect 0.813x1.905 smd: 1(-5.625,4.875) 2(-4.375,4.875) 3(-3.125,4.875) 4(-1.875,4.875) 5(-0.625,4.875) 6(0.625,4.875) 7(1.875,4.875) 8(3.125,4.875) 9(4.375,4.875) 10(5.625,4.875)
  rect 1.295x3.353 smd: 11(-8.475,0) 12(8.475,0)
50224-0020N-W02
  rect 0.61x1.549 smd: 1(-0.5,3.876) 2(0.5,3.876)
  rect 1.194x1.803 smd: 3(-1.797,0) 4(1.797,0)
50224-0040N-001
  rect 0.61x1.549 smd: 1(-1.5,3.875) 2(-0.5,3.875) 3(0.5,3.875) 4(1.5,3.875)
  rect 1.194x1.803 smd: 5(-2.797,0) 6(2.797,0)
50224-0060N-W01
  rect 0.406x1.549 smd: 1(-2.5,3.875) 2(-1.5,3.875) 3(-0.5,3.875) 4(0.5,3.875) 5(1.5,3.875) 6(2.5,3.875)
  rect 1.194x1.803 smd: 7(-3.8,0) 8(3.8,0)
50699-03001-W01
  rect 0.229x0.813 smd: 1(-11.6,3.3) 2(-10.8,3.3) 3(-10,3.3) 4(-9.2,3.3) 5(-8.4,3.3) 6(-7.6,3.3) 7(-6.8,3.3) 8(-6,3.3) 9(-5.2,3.3) 10(-4.4,3.3) 11(-3.6,3.3) 12(-2.8,3.3) 13(-2,3.3) 14(-1.2,3.3) 15(-0.4,3.3) 16(0.4,3.3) 17(1.2,3.3) 18(2,3.3) 19(2.8,3.3) 20(3.6,3.3) 21(4.4,3.3) 22(5.2,3.3) 23(6,3.3) 24(6.8,3.3) 25(7.6,3.3) 26(8.4,3.3) 27(9.2,3.3) 28(10,3.3) 29(10.8,3.3) 30(11.6,3.3)
  rect 0.559x1.295 smd: 31(-13.075,0) 32(13.075,0)
51540-04001-W01
  rect 0.305x0.838 smd: 1(-9.75,3.175) 2(-9.25,3.175) 3(-8.75,3.175) 4(-8.25,3.175) 5(-7.75,3.175) 6(-7.25,3.175) 7(-6.75,3.175) 8(-6.25,3.175) 9(-5.75,3.175) 10(-5.25,3.175) 11(-4.75,3.175) 12(-4.25,3.175) 13(-3.75,3.175) 14(-3.25,3.175) 15(-2.75,3.175) 16(-2.25,3.175) 17(-1.75,3.175) 18(-1.25,3.175) 19(-0.75,3.175) 20(-0.25,3.175) 21(0.25,3.175) 22(0.75,3.175) 23(1.25,3.175) 24(1.75,3.175) 25(2.25,3.175) 26(2.75,3.175) 27(3.25,3.175) 28(3.75,3.175) 29(4.25,3.175) 30(4.75,3.175) 31(5.25,3.175) 32(5.75,3.175) 33(6.25,3.175) 34(6.75,3.175) 35(7.25,3.175) 36(7.75,3.175) 37(8.25,3.175) 38(8.75,3.175) 39(9.25,3.175) 40(9.75,3.175)
  rect 0.813x2.007 smd: 41(-11.45,0) 42(11.45,0)
196574-08021-3
  rect 0.305x0.991 smd: 1(-3.5,3.2) 2(-2.5,3.2) 3(-1.5,3.2) 4(-0.5,3.2) 5(0.5,3.2) 6(1.5,3.2) 7(2.5,3.2) 8(3.5,3.2)
  rect 0.406x0.991 smd: 9(-5.185,0) 10(5.185,0)
AFTE14P-75
  round 0.356 smd: 1(0,0)
ARES2H16
  rect 0.457x0.635 smd: 1(-0.335,-0.44) 2(0.335,-0.44) 3(0.335,0.44) 4(-0.335,0.44)
ARES2H18
  rect 0.457x0.635 smd: 1(-0.335,-0.44) 2(0.335,-0.44) 3(0.335,0.44) 4(-0.335,0.44)
ARES8-CN24-MUH20
  rect 0.457x0.61 smd: 1(-0.838,-0.445) 4(0.838,-0.445) 5(0.838,0.445) 8(-0.838,0.445)
  rect 0.305x0.61 smd: 2(-0.25,-0.445) 3(0.25,-0.445) 6(0.25,0.445) 7(-0.25,0.445)
ARES8-CN24-UH20
  rect 0.457x0.61 smd: 1(-0.838,-0.445) 4(0.838,-0.445) 5(0.838,0.445) 8(-0.838,0.445)
  rect 0.305x0.61 smd: 2(-0.25,-0.445) 3(0.25,-0.445) 6(0.25,0.445) 7(-0.25,0.445)
ARES8-CN24H20
  rect 0.457x0.559 smd: 1(-0.838,-0.483) 4(0.838,-0.483) 5(0.838,0.483) 8(-0.838,0.483)
  rect 0.305x0.559 smd: 2(-0.25,-0.483) 3(0.25,-0.483) 6(0.25,0.483) 7(-0.25,0.483)
BGA153G115130-2H40
  oval 0.229x0.356 smd: A1(-3.25,3.25) A2(-2.75,3.25) A3(-2.25,3.25) A4(-1.75,3.25) A5(-1.25,3.25) A6(-0.75,3.25)
  round 0.356 smd: A7(-0.25,3.25) A8(0.25,3.25) A9(0.75,3.25) A10(1.25,3.25) A11(1.75,3.25) A12(2.25,3.25) A13(2.75,3.25) A14(3.25,3.25) B2(-2.75,2.75) B3(-2.25,2.75) B4(-1.75,2.75) B5(-1.25,2.75) B6(-0.75,2.75) B7(-0.25,2.75) B8(0.25,2.75) B9(0.75,2.75) B10(1.25,2.75) B11(1.75,2.75) B12(2.25,2.75) B13(2.75,2.75) B14(3.25,2.75) C2(-2.75,2.25) C3(-2.25,2.25) C4(-1.75,2.25) C5(-1.25,2.25) C6(-0.75,2.25) C7(-0.25,2.25) C8(0.25,2.25) C9(0.75,2.25) C10(1.25,2.25) C11(1.75,2.25) C12(2.25,2.25) C13(2.75,2.25) C14(3.25,2.25) D1(-3.25,1.75) D2(-2.75,1.75) D3(-2.25,1.75) D4(-1.75,1.75) D12(2.25,1.75) D13(2.75,1.75) D14(3.25,1.75) E1(-3.25,1.25) E2(-2.75,1.25) E3(-2.25,1.25) E5(-1.25,1.25) E6(-0.75,1.25) E7(-0.25,1.25) E8(0.25,1.25) E9(0.75,1.25) E10(1.25,1.25) E12(2.25,1.25) E13(2.75,1.25) E14(3.25,1.25) F1(-3.25,0.75) F2(-2.75,0.75) F3(-2.25,0.75) F5(-1.25,0.75) F10(1.25,0.75) F12(2.25,0.75) F13(2.75,0.75) F14(3.25,0.75) G1(-3.25,0.25) G2(-2.75,0.25) G3(-2.25,0.25) G5(-1.25,0.25) G10(1.25,0.25) G12(2.25,0.25) G13(2.75,0.25) G14(3.25,0.25) H1(-3.25,-0.25) H2(-2.75,-0.25) H3(-2.25,-0.25) H5(-1.25,-0.25) H10(1.25,-0.25) H12(2.25,-0.25) H13(2.75,-0.25) H14(3.25,-0.25) J1(-3.25,-0.75) J2(-2.75,-0.75) J3(-2.25,-0.75) J5(-1.25,-0.75) J10(1.25,-0.75) J12(2.25,-0.75) J13(2.75,-0.75) J14(3.25,-0.75) K1(-3.25,-1.25) K2(-2.75,-1.25) K3(-2.25,-1.25) K5(-1.25,-1.25) K6(-0.75,-1.25) K7(-0.25,-1.25) K8(0.25,-1.25) K9(0.75,-1.25) K10(1.25,-1.25) K12(2.25,-1.25) K13(2.75,-1.25) K14(3.25,-1.25) L1(-3.25,-1.75) L2(-2.75,-1.75) L3(-2.25,-1.75) L12(2.25,-1.75) L13(2.75,-1.75) L14(3.25,-1.75) M2(-2.75,-2.25) M3(-2.25,-2.25) M4(-1.75,-2.25) M5(-1.25,-2.25) M6(-0.75,-2.25) M7(-0.25,-2.25) M8(0.25,-2.25) M9(0.75,-2.25) M10(1.25,-2.25) M11(1.75,-2.25) M12(2.25,-2.25) M13(2.75,-2.25) M14(3.25,-2.25) N2(-2.75,-2.75) N3(-2.25,-2.75) N4(-1.75,-2.75) N5(-1.25,-2.75) N6(-0.75,-2.75) N7(-0.25,-2.75) N8(0.25,-2.75) N9(0.75,-2.75) N10(1.25,-2.75) N11(1.75,-2.75) N12(2.25,-2.75) N13(2.75,-2.75) N14(3.25,-2.75) P2(-2.75,-3.25) P3(-2.25,-3.25) P4(-1.75,-3.25) P5(-1.25,-3.25) P6(-0.75,-3.25) P7(-0.25,-3.25) P8(0.25,-3.25) P9(0.75,-3.25) P10(1.25,-3.25) P11(1.75,-3.25) P12(2.25,-3.25) P13(2.75,-3.25) P14(3.25,-3.25)
  oval 0.356x0.229 smd: B1(-3.25,2.75) C1(-3.25,2.25) M1(-3.25,-2.25) N1(-3.25,-2.75) P1(-3.25,-3.25)
BGA769M24D5H67
  round 0.4 smd: A2(-10.7,11.3) A3(-9.95,11.3) A39(9.95,11.3) A40(10.7,11.3) AA4(-9.2,0) AA5(-8.4,0) AA7(-7.6,0) AA8(-6.8,0) AA10(-6,0) AA11(-5,0) AA13(-4,0) AA15(-3,0) AA17(-2,0) AA19(-1,0) AA21(0,0) AA23(1,0) AA25(2,0) AA27(3,0) AA29(4,0) AA31(5,0) AA32(6,0) AA34(6.8,0) AA35(7.6,0) AA37(8.4,0) AA38(9.2,0) AC4(-9.2,-1.1) AC5(-8.4,-1.1) AC7(-7.6,-1.1) AC8(-6.8,-1.1) AC10(-6,-1.1) AC11(-5,-1) AC13(-4,-1) AC15(-3,-1) AC17(-2,-1) AC19(-1,-1) AC21(0,-1) AC23(1,-1) AC25(2,-1) AC27(3,-1) AC29(4,-1) AC31(5,-1) AC32(6,-1.1) AC34(6.8,-1.1) AC35(7.6,-1.1) AC37(8.4,-1.1) AC38(9.2,-1.1) AE4(-9.2,-2.2) AE5(-8.4,-2.2) AE7(-7.6,-2.2) AE8(-6.8,-2.2) AE10(-6,-2.2) AE11(-5,-2) AE13(-4,-2) AE15(-3,-2) AE17(-2,-2) AE19(-1,-2) AE21(0,-2) AE23(1,-2) AE25(2,-2) AE27(3,-2) AE29(4,-2) AE31(5,-2) AE32(6,-2.2) AE34(6.8,-2.2) AE35(7.6,-2.2) AE37(8.4,-2.2) AE38(9.2,-2.2) AG4(-9.2,-3.3) AG5(-8.4,-3.3) AG7(-7.6,-3.3) AG8(-6.8,-3.3) AG10(-6,-3.3) AG11(-5,-3) AG13(-4,-3) AG15(-3,-3) AG17(-2,-3) AG19(-1,-3) AG21(0,-3) AG23(1,-3) AG25(2,-3) AG27(3,-3) AG29(4,-3) AG31(5,-3) AG32(6,-3.3) AG34(6.8,-3.3) AG35(7.6,-3.3) AG37(8.4,-3.3) AG38(9.2,-3.3) AJ4(-9.2,-4.4) AJ5(-8.4,-4.4) AJ7(-7.6,-4.4) AJ8(-6.8,-4.4) AJ10(-6,-4.4) AJ11(-5,-4) AJ13(-4,-4) AJ15(-3,-4) AJ17(-2,-4) AJ19(-1,-4) AJ21(0,-4) AJ23(1,-4) AJ25(2,-4) AJ27(3,-4) AJ29(4,-4) AJ31(5,-4) AJ32(6,-4.4) AJ34(6.8,-4.4) AJ35(7.6,-4.4) AJ37(8.4,-4.4) AJ38(9.2,-4.4) AL4(-9.2,-5.5) AL5(-8.4,-5.5) AL7(-7.6,-5.5) AL8(-6.8,-5.5) AL10(-6,-5.5) AL11(-5,-5) AL13(-4,-5) AL15(-3,-5) AL17(-2,-5) AL19(-1,-5) AL21(0,-5) AL23(1,-5) AL25(2,-5) AL27(3,-5) AL29(4,-5) AL31(5,-5) AL32(6,-5.5) AL34(6.8,-5.5) AL35(7.6,-5.5) AL37(8.4,-5.5) AL38(9.2,-5.5) AM11(-5.5,-6) AM13(-4.4,-6) AM15(-3.3,-6) AM17(-2.2,-6) AM19(-1.1,-6) AM21(0,-6) AM23(1.1,-6) AM25(2.2,-6) AM27(3.3,-6) AM29(4.4,-6) AM31(5.5,-6) AN4(-9.2,-6.6) AN5(-8.4,-6.6) AN7(-7.6,-6.6) AN8(-6.8,-6.6) AN34(6.8,-6.6) AN35(7.6,-6.6) AN37(8.4,-6.6) AN38(9.2,-6.6) AP11(-5.5,-6.8) AP13(-4.4,-6.8) AP15(-3.3,-6.8) AP17(-2.2,-6.8) AP19(-1.1,-6.8) AP21(0,-6.8) AP23(1.1,-6.8) AP25(2.2,-6.8) AP27(3.3,-6.8) AP29(4.4,-6.8) AP31(5.5,-6.8) AR4(-9.2,-7.7) AR5(-8.4,-7.7) AR7(-7.6,-7.7) AR11(-5.5,-7.6) AR13(-4.4,-7.6) AR15(-3.3,-7.6) AR17(-2.2,-7.6) AR19(-1.1,-7.6) AR21(0,-7.6) AR23(1.1,-7.6) AR25(2.2,-7.6) AR27(3.3,-7.6) AR29(4.4,-7.6) AR31(5.5,-7.6) AR35(7.6,-7.7) AR37(8.4,-7.7) AR38(9.2,-7.7) AU4(-9.2,-8.8) AU7(-7.7,-8.4) AU9(-6.6,-8.4) AU11(-5.5,-8.4) AU13(-4.4,-8.4) AU15(-3.3,-8.4) AU17(-2.2,-8.4) AU19(-1.1,-8.4) AU21(0,-8.4) AU23(1.1,-8.4) AU25(2.2,-8.4) AU27(3.3,-8.4) AU29(4.4,-8.4) AU31(5.5,-8.4) AU33(6.6,-8.4) AU35(7.7,-8.4) AU38(9.2,-8.8) AV7(-7.7,-9.2) AV9(-6.6,-9.2) AV11(-5.5,-9.2) AV13(-4.4,-9.2) AV15(-3.3,-9.2) AV17(-2.2,-9.2) AV19(-1.1,-9.2) AV21(0,-9.2) AV23(1.1,-9.2) AV25(2.2,-9.2) AV27(3.3,-9.2) AV29(4.4,-9.2) AV31(5.5,-9.2) AV33(6.6,-9.2) AV35(7.7,-9.2) AW1(-11.3,-9.95) AW41(11.3,-9.95) AY1(-11.3,-10.7) AY2(-10.6,-10.6) AY40(10.6,-10.6) AY41(11.3,-10.7) B1(-11.3,10.7) B2(-10.6,10.6) B40(10.6,10.6) B41(11.3,10.7) BA2(-10.7,-11.3) BA3(-9.95,-11.3) BA39(9.95,-11.3) BA40(10.7,-11.3) C1(-11.3,9.95) C41(11.3,9.95) D7(-7.7,9.2) D9(-6.6,9.2) D11(-5.5,9.2) D13(-4.4,9.2) D15(-3.3,9.2) D17(-2.2,9.2) D19(-1.1,9.2) D21(0,9.2) D23(1.1,9.2) D25(2.2,9.2) D27(3.3,9.2) D29(4.4,9.2) D31(5.5,9.2) D33(6.6,9.2) D35(7.7,9.2) E4(-9.2,8.8) E7(-7.7,8.4) E9(-6.6,8.4) E11(-5.5,8.4) E13(-4.4,8.4) E15(-3.3,8.4) E17(-2.2,8.4) E19(-1.1,8.4) E21(0,8.4) E23(1.1,8.4) E25(2.2,8.4) E27(3.3,8.4) E29(4.4,8.4) E31(5.5,8.4) E33(6.6,8.4) E35(7.7,8.4) E38(9.2,8.8) G4(-9.2,7.7) G5(-8.4,7.7) G7(-7.6,7.7) G11(-5.5,7.6) G13(-4.4,7.6) G15(-3.3,7.6) G17(-2.2,7.6) G19(-1.1,7.6) G21(0,7.6) G23(1.1,7.6) G25(2.2,7.6) G27(3.3,7.6) G29(4.4,7.6) G31(5.5,7.6) G35(7.6,7.7) G37(8.4,7.7) G38(9.2,7.7) H11(-5.5,6.8) H13(-4.4,6.8) H15(-3.3,6.8) H17(-2.2,6.8) H19(-1.1,6.8) H21(0,6.8) H23(1.1,6.8) H25(2.2,6.8) H27(3.3,6.8) H29(4.4,6.8) H31(5.5,6.8) J4(-9.2,6.6) J5(-8.4,6.6) J7(-7.6,6.6) J8(-6.8,6.6) J34(6.8,6.6) J35(7.6,6.6) J37(8.4,6.6) J38(9.2,6.6) K11(-5.5,6) K13(-4.4,6) K15(-3.3,6) K17(-2.2,6) K19(-1.1,6) K21(0,6) K23(1.1,6) K25(2.2,6) K27(3.3,6) K29(4.4,6) K31(5.5,6) L4(-9.2,5.5) L5(-8.4,5.5) L7(-7.6,5.5) L8(-6.8,5.5) L10(-6,5.5) L11(-5,5) L13(-4,5) L15(-3,5) L17(-2,5) L19(-1,5) L21(0,5) L23(1,5) L25(2,5) L27(3,5) L29(4,5) L31(5,5) L32(6,5.5) L34(6.8,5.5) L35(7.6,5.5) L37(8.4,5.5) L38(9.2,5.5) N4(-9.2,4.4) N5(-8.4,4.4) N7(-7.6,4.4) N8(-6.8,4.4) N10(-6,4.4) N11(-5,4) N13(-4,4) N15(-3,4) N17(-2,4) N19(-1,4) N21(0,4) N23(1,4) N25(2,4) N27(3,4) N29(4,4) N31(5,4) N32(6,4.4) N34(6.8,4.4) N35(7.6,4.4) N37(8.4,4.4) N38(9.2,4.4) R4(-9.2,3.3) R5(-8.4,3.3) R7(-7.6,3.3) R8(-6.8,3.3) R10(-6,3.3) R11(-5,3) R13(-4,3) R15(-3,3) R17(-2,3) R19(-1,3) R21(0,3) R23(1,3) R25(2,3) R27(3,3) R29(4,3) R31(5,3) R32(6,3.3) R34(6.8,3.3) R35(7.6,3.3) R37(8.4,3.3) R38(9.2,3.3) U4(-9.2,2.2) U5(-8.4,2.2) U7(-7.6,2.2) U8(-6.8,2.2) U10(-6,2.2) U11(-5,2) U13(-4,2) U15(-3,2) U17(-2,2) U19(-1,2) U21(0,2) U23(1,2) U25(2,2) U27(3,2) U29(4,2) U31(5,2) U32(6,2.2) U34(6.8,2.2) U35(7.6,2.2) U37(8.4,2.2) U38(9.2,2.2) W4(-9.2,1.1) W5(-8.4,1.1) W7(-7.6,1.1) W8(-6.8,1.1) W10(-6,1.1) W11(-5,1) W13(-4,1) W15(-3,1) W17(-2,1) W19(-1,1) W21(0,1) W23(1,1) W25(2,1) W27(3,1) W29(4,1) W31(5,1) W32(6,1.1) W34(6.8,1.1) W35(7.6,1.1) W37(8.4,1.1) W38(9.2,1.1)
  round 0.3 smd: A4(-9.35,10.95) A5(-8.8,11.3) A6(-8.25,10.95) A7(-7.7,11.3) A8(-7.15,10.95) A9(-6.6,11.3) A10(-6.05,10.95) A11(-5.5,11.3) A12(-4.95,10.95) A13(-4.4,11.3) A14(-3.85,10.95) A15(-3.3,11.3) A16(-2.75,10.95) A17(-2.2,11.3) A18(-1.65,10.95) A19(-1.1,11.3) A20(-0.55,10.95) A21(0,11.3) A22(0.55,10.95) A23(1.1,11.3) A24(1.65,10.95) A25(2.2,11.3) A26(2.75,10.95) A27(3.3,11.3) A28(3.85,10.95) A29(4.4,11.3) A30(4.95,10.95) A31(5.5,11.3) A32(6.05,10.95) A33(6.6,11.3) A34(7.15,10.95) A35(7.7,11.3) A36(8.25,10.95) A37(8.8,11.3) A38(9.35,10.95) AA1(-11.3,0) AA2(-10.6,0) AA3(-9.9,0) AA39(9.9,0) AA40(10.6,0) AA41(11.3,0) AB1(-10.95,-0.55) AB2(-10.25,-0.55) AB40(10.25,-0.55) AB41(10.95,-0.55) AC1(-11.3,-1.1) AC2(-10.6,-1.1) AC3(-9.9,-1.1) AC39(9.9,-1.1) AC40(10.6,-1.1) AC41(11.3,-1.1) AD1(-10.95,-1.65) AD2(-10.25,-1.65) AD40(10.25,-1.65) AD41(10.95,-1.65) AE1(-11.3,-2.2) AE2(-10.6,-2.2) AE3(-9.9,-2.2) AE39(9.9,-2.2) AE40(10.6,-2.2) AE41(11.3,-2.2) AF1(-10.95,-2.75) AF2(-10.25,-2.75) AF40(10.25,-2.75) AF41(10.95,-2.75) AG1(-11.3,-3.3) AG2(-10.6,-3.3) AG3(-9.9,-3.3) AG39(9.9,-3.3) AG40(10.6,-3.3) AG41(11.3,-3.3) AH1(-10.95,-3.85) AH2(-10.25,-3.85) AH40(10.25,-3.85) AH41(10.95,-3.85) AJ1(-11.3,-4.4) AJ2(-10.6,-4.4) AJ3(-9.9,-4.4) AJ39(9.9,-4.4) AJ40(10.6,-4.4) AJ41(11.3,-4.4) AK1(-10.95,-4.95) AK2(-10.25,-4.95) AK40(10.25,-4.95) AK41(10.95,-4.95) AL1(-11.3,-5.5) AL2(-10.6,-5.5) AL3(-9.9,-5.5) AL39(9.9,-5.5) AL40(10.6,-5.5) AL41(11.3,-5.5) AM1(-10.95,-6.05) AM2(-10.25,-6.05) AM40(10.25,-6.05) AM41(10.95,-6.05) AN1(-11.3,-6.6) AN2(-10.6,-6.6) AN3(-9.9,-6.6) AN39(9.9,-6.6) AN40(10.6,-6.6) AN41(11.3,-6.6) AP1(-10.95,-7.15) AP2(-10.25,-7.15) AP40(10.25,-7.15) AP41(10.95,-7.15) AR1(-11.3,-7.7) AR2(-10.6,-7.7) AR3(-9.9,-7.7) AR39(9.9,-7.7) AR40(10.6,-7.7) AR41(11.3,-7.7) AT1(-10.95,-8.25) AT2(-10.25,-8.25) AT40(10.25,-8.25) AT41(10.95,-8.25) AU1(-11.3,-8.8) AU2(-10.6,-8.8) AU3(-9.9,-8.8) AU39(9.9,-8.8) AU40(10.6,-8.8) AU41(11.3,-8.8) AV1(-10.95,-9.35) AV2(-10.25,-9.35) AV40(10.25,-9.35) AV41(10.95,-9.35) AW2(-10.6,-9.9) AW3(-9.9,-9.9) AW5(-8.8,-9.9) AW7(-7.7,-9.9) AW9(-6.6,-9.9) AW11(-5.5,-9.9) AW13(-4.4,-9.9) AW15(-3.3,-9.9) AW17(-2.2,-9.9) AW19(-1.1,-9.9) AW21(0,-9.9) AW23(1.1,-9.9) AW25(2.2,-9.9) AW27(3.3,-9.9) AW29(4.4,-9.9) AW31(5.5,-9.9) AW33(6.6,-9.9) AW35(7.7,-9.9) AW37(8.8,-9.9) AW39(9.9,-9.9) AW40(10.6,-9.9) AY3(-9.9,-10.6) AY4(-9.35,-10.25) AY5(-8.8,-10.6) AY6(-8.25,-10.25) AY7(-7.7,-10.6) AY8(-7.15,-10.25) AY9(-6.6,-10.6) AY10(-6.05,-10.25) AY11(-5.5,-10.6) AY12(-4.95,-10.25) AY13(-4.4,-10.6) AY14(-3.85,-10.25) AY15(-3.3,-10.6) AY16(-2.75,-10.25) AY17(-2.2,-10.6) AY18(-1.65,-10.25) AY19(-1.1,-10.6) AY20(-0.55,-10.25) AY21(0,-10.6) AY22(0.55,-10.25) AY23(1.1,-10.6) AY24(1.65,-10.25) AY25(2.2,-10.6) AY26(2.75,-10.25) AY27(3.3,-10.6) AY28(3.85,-10.25) AY29(4.4,-10.6) AY30(4.95,-10.25) AY31(5.5,-10.6) AY32(6.05,-10.25) AY33(6.6,-10.6) AY34(7.15,-10.25) AY35(7.7,-10.6) AY36(8.25,-10.25) AY37(8.8,-10.6) AY38(9.35,-10.25) AY39(9.9,-10.6) B3(-9.9,10.6) B4(-9.35,10.25) B5(-8.8,10.6) B6(-8.25,10.25) B7(-7.7,10.6) B8(-7.15,10.25) B9(-6.6,10.6) B10(-6.05,10.25) B11(-5.5,10.6) B12(-4.95,10.25) B13(-4.4,10.6) B14(-3.85,10.25) B15(-3.3,10.6) B16(-2.75,10.25) B17(-2.2,10.6) B18(-1.65,10.25) B19(-1.1,10.6) B20(-0.55,10.25) B21(0,10.6) B22(0.55,10.25) B23(1.1,10.6) B24(1.65,10.25) B25(2.2,10.6) B26(2.75,10.25) B27(3.3,10.6) B28(3.85,10.25) B29(4.4,10.6) B30(4.95,10.25) B31(5.5,10.6) B32(6.05,10.25) B33(6.6,10.6) B34(7.15,10.25) B35(7.7,10.6) B36(8.25,10.25) B37(8.8,10.6) B38(9.35,10.25) B39(9.9,10.6) BA4(-9.35,-10.95) BA5(-8.8,-11.3) BA6(-8.25,-10.95) BA7(-7.7,-11.3) BA8(-7.15,-10.95) BA9(-6.6,-11.3) BA10(-6.05,-10.95) BA11(-5.5,-11.3) BA12(-4.95,-10.95) BA13(-4.4,-11.3) BA14(-3.85,-10.95) BA15(-3.3,-11.3) BA16(-2.75,-10.95) BA17(-2.2,-11.3) BA18(-1.65,-10.95) BA19(-1.1,-11.3) BA20(-0.55,-10.95) BA21(0,-11.3) BA22(0.55,-10.95) BA23(1.1,-11.3) BA24(1.65,-10.95) BA25(2.2,-11.3) BA26(2.75,-10.95) BA27(3.3,-11.3) BA28(3.85,-10.95) BA29(4.4,-11.3) BA30(4.95,-10.95) BA31(5.5,-11.3) BA32(6.05,-10.95) BA33(6.6,-11.3) BA34(7.15,-10.95) BA35(7.7,-11.3) BA36(8.25,-10.95) BA37(8.8,-11.3) BA38(9.35,-10.95) C2(-10.6,9.9) C3(-9.9,9.9) C5(-8.8,9.9) C7(-7.7,9.9) C9(-6.6,9.9) C11(-5.5,9.9) C13(-4.4,9.9) C15(-3.3,9.9) C17(-2.2,9.9) C19(-1.1,9.9) C21(0,9.9) C23(1.1,9.9) C25(2.2,9.9) C27(3.3,9.9) C29(4.4,9.9) C31(5.5,9.9) C33(6.6,9.9) C35(7.7,9.9) C37(8.8,9.9) C39(9.9,9.9) C40(10.6,9.9) D1(-10.95,9.35) D2(-10.25,9.35) D40(10.25,9.35) D41(10.95,9.35) E1(-11.3,8.8) E2(-10.6,8.8) E3(-9.9,8.8) E39(9.9,8.8) E40(10.6,8.8) E41(11.3,8.8) F1(-10.95,8.25) F2(-10.25,8.25) F40(10.25,8.25) F41(10.95,8.25) G1(-11.3,7.7) G2(-10.6,7.7) G3(-9.9,7.7) G39(9.9,7.7) G40(10.6,7.7) G41(11.3,7.7) H1(-10.95,7.15) H2(-10.25,7.15) H40(10.25,7.15) H41(10.95,7.15) J1(-11.3,6.6) J2(-10.6,6.6) J3(-9.9,6.6) J39(9.9,6.6) J40(10.6,6.6) J41(11.3,6.6) K1(-10.95,6.05) K2(-10.25,6.05) K40(10.25,6.05) K41(10.95,6.05) L1(-11.3,5.5) L2(-10.6,5.5) L3(-9.9,5.5) L39(9.9,5.5) L40(10.6,5.5) L41(11.3,5.5) M1(-10.95,4.95) M2(-10.25,4.95) M40(10.25,4.95) M41(10.95,4.95) N1(-11.3,4.4) N2(-10.6,4.4) N3(-9.9,4.4) N39(9.9,4.4) N40(10.6,4.4) N41(11.3,4.4) P1(-10.95,3.85) P2(-10.25,3.85) P40(10.25,3.85) P41(10.95,3.85) R1(-11.3,3.3) R2(-10.6,3.3) R3(-9.9,3.3) R39(9.9,3.3) R40(10.6,3.3) R41(11.3,3.3) T1(-10.95,2.75) T2(-10.25,2.75) T40(10.25,2.75) T41(10.95,2.75) U1(-11.3,2.2) U2(-10.6,2.2) U3(-9.9,2.2) U39(9.9,2.2) U40(10.6,2.2) U41(11.3,2.2) V1(-10.95,1.65) V2(-10.25,1.65) V40(10.25,1.65) V41(10.95,1.65) W1(-11.3,1.1) W2(-10.6,1.1) W3(-9.9,1.1) W39(9.9,1.1) W40(10.6,1.1) W41(11.3,1.1) Y1(-10.95,0.55) Y2(-10.25,0.55) Y40(10.25,0.55) Y41(10.95,0.55)
